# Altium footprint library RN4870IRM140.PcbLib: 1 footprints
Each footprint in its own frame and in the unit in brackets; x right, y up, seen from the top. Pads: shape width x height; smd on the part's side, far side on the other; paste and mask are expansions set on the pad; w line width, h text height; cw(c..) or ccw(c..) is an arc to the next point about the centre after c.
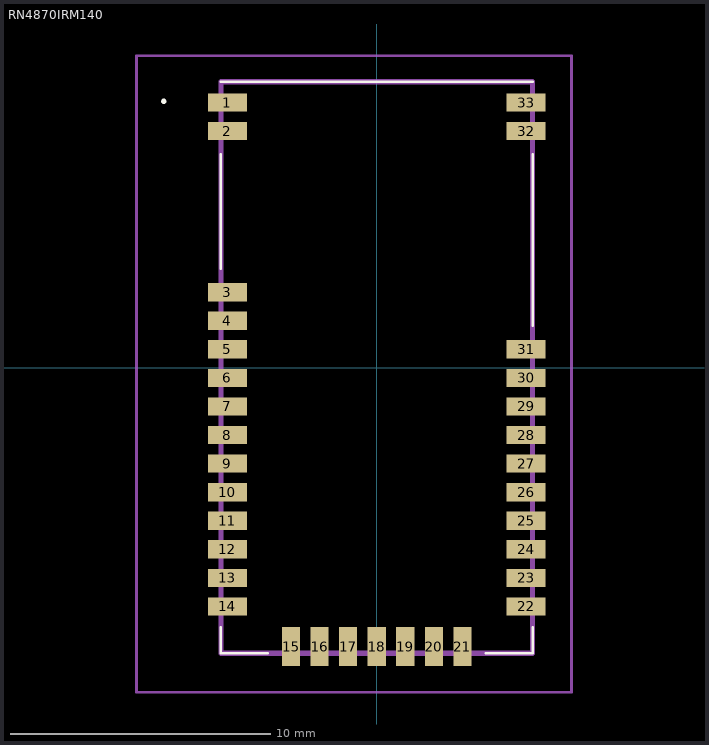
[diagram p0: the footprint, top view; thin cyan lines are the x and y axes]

## RN4870IRM140 [mm]
pads (33):
  rect 1.5x0.7 smd: 1(-5.75,10.2) 2(-5.75,9.1) 3(-5.75,2.9) 4(-5.75,1.8) 5(-5.75,0.7) 6(-5.75,-0.4) 7(-5.75,-1.5) 8(-5.75,-2.6) 9(-5.75,-3.7) 10(-5.75,-4.8) 11(-5.75,-5.9) 12(-5.75,-7) 13(-5.75,-8.1) 14(-5.75,-9.2) 22(5.75,-9.2) 23(5.75,-8.1) 24(5.75,-7) 25(5.75,-5.9) 26(5.75,-4.8) 27(5.75,-3.7) 28(5.75,-2.6) 29(5.75,-1.5) 30(5.75,-0.4) 31(5.75,0.7) 32(5.75,9.1) 33(5.75,10.2)
  rect 0.7x1.5 smd: 15(-3.3,-10.75) 16(-2.2,-10.75) 17(-1.1,-10.75) 18(0,-10.75) 19(1.1,-10.75) 20(2.2,-10.75) 21(3.3,-10.75)
Top Overlay:
  lines w0.1: -6,-10 -6,-11 -4.2,-11 ; -6,3.8 -6,8.2 ; -6,11 6,11 ; 4.2,-11 6,-11 6,-10 ; 6,1.6 6,8.2 ; -8.2,10.2 -8.2,10.2 ; -8.2,10.2 ccw(c-8.2,10.25) -8.2,10.3 ; -8.2,10.2 cw(c-8.2,10.25) -8.2,10.3 ; -8.2,10.3 -8.2,10.3
Mechanical 15:
  lines w0.2: -6,-11 6,-11 6,11 -6,11 -6,-11
Mechanical 20:
  lines w0.1: -9.25,-12.5 7.5,-12.5 7.5,12 -9.25,12 -9.25,-12.5
3D body "RN4870-I_RM140.stp": height 5.8, standoff -4.65, extent -10,-3.376 10,3.376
